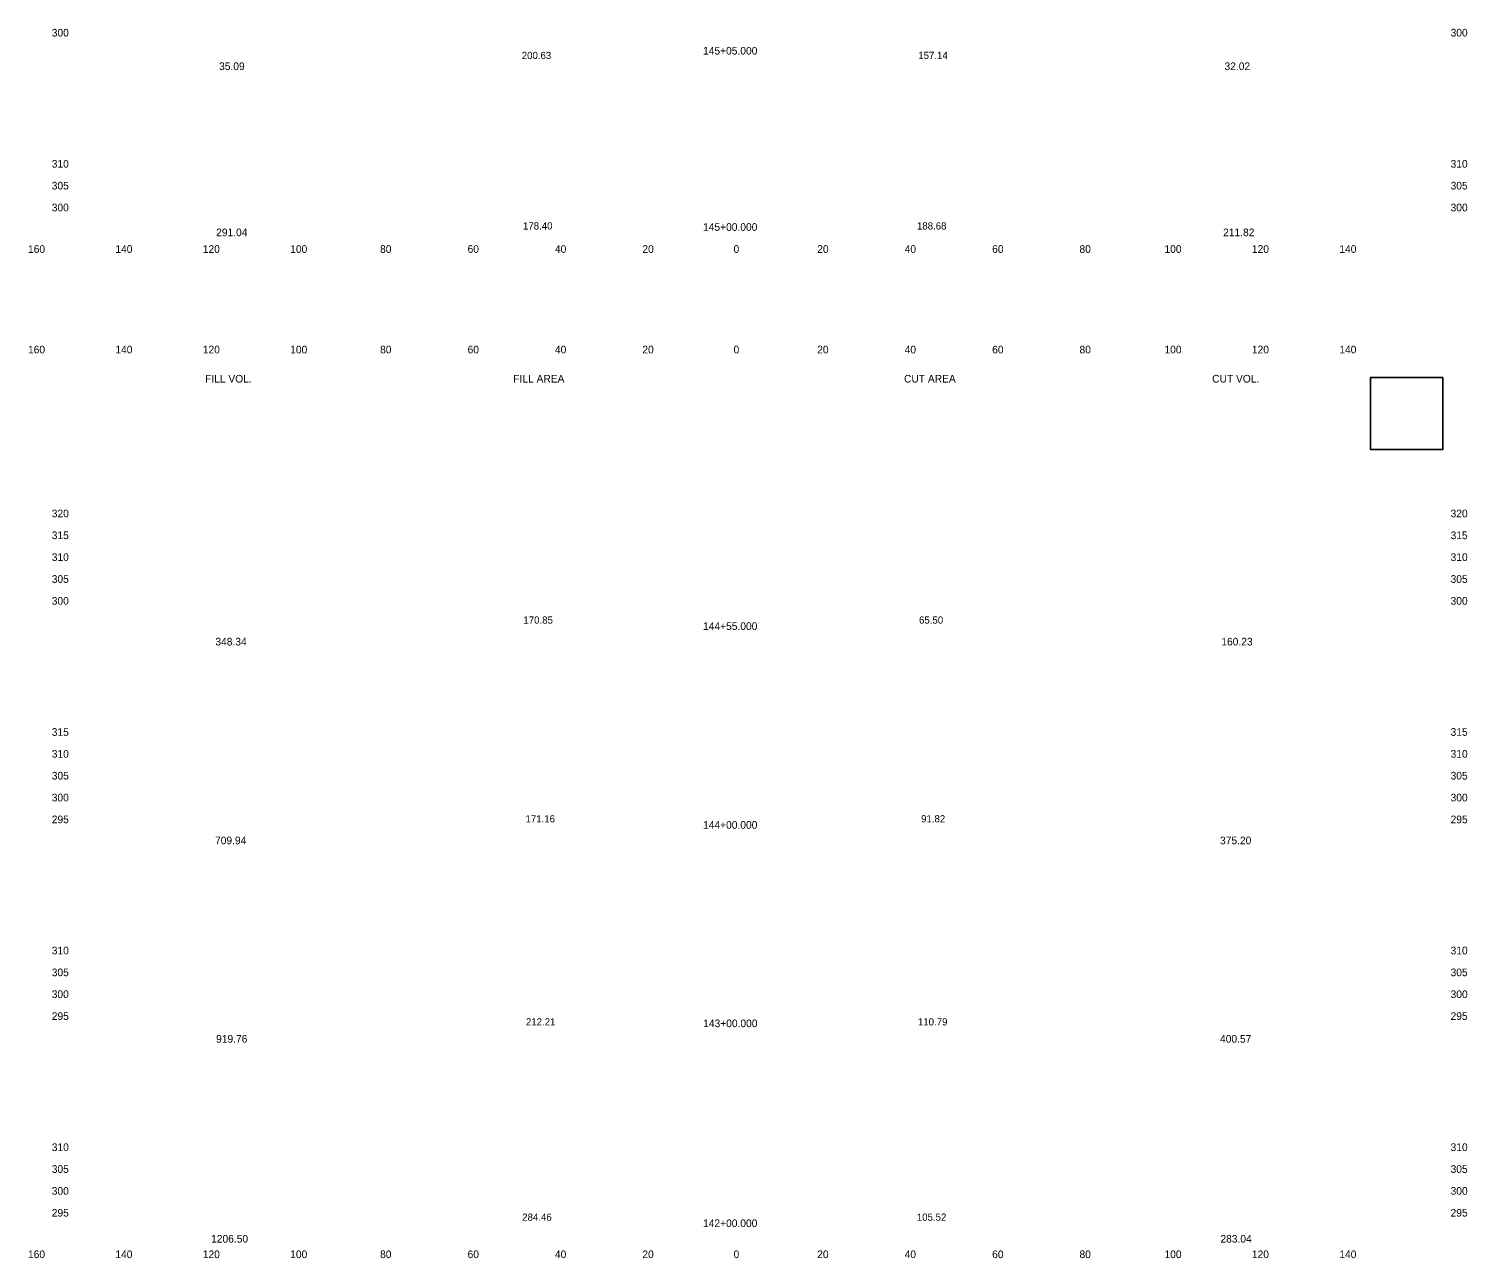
# Model space of a CAD drawing. Extents: x 21477 to 21806, y 6470 to 11049.
# Drawn here: x 21477.1 to 21806.1, y 9920.3 to 10201.6 of the extents above; entities that cross this region are included whole.
import ezdxf

# ---------------------------------------------------------------- set-up
doc = ezdxf.new("R2010")
doc.units = 0
for name, color, linetype in [('SHEET_CONSULTANT_STAMP', 7, 'Continuous'), ('XS_SHEET_EW_TX_AREA', 7, 'Continuous'), ('XS_SHEET_EW_TX_VOLUME', 7, 'Continuous'), ('XS_SHEET_LABELS_ELEVATION', 7, 'Continuous'), ('XS_SHEET_LABELS_OFFSET', 7, 'Continuous'), ('XS_SHEET_LABELS_STATION', 7, 'Continuous'), ('XS_SHEET_TX', 7, 'Continuous')]:
    doc.layers.add(name, color=color, linetype=linetype)

msp = doc.modelspace()

# ---------------------------------------------------------------- linework, layer by layer
at = {"layer": 'SHEET_CONSULTANT_STAMP'}
msp.add_lwpolyline([(21784.04, 10105.34), (21800.54, 10105.34), (21800.54, 10121.84), (21784.04, 10121.84)], close=True, dxfattribs=at)

# ---------------------------------------------------------------- texts
at = {"layer": 'XS_SHEET_EW_TX_AREA'}
for s, p in [(' 200.63 ', (21589.24, 10194.69)), (' 157.14 ', (21679.95, 10194.69)), (' 178.40 ', (21589.53, 10155.68)), (' 188.68 ', (21679.65, 10155.68)), (' 170.85 ', (21589.62, 10065.51)), (' 65.50 ', (21680.13, 10065.51)), (' 171.16 ', (21590.1, 10020.03)), (' 91.82 ', (21680.6, 10020.03)), (' 212.21 ', (21590.2, 9973.57)), (' 110.79 ', (21679.87, 9973.57)), (' 284.46 ', (21589.35, 9928.89)), (' 105.52 ', (21679.62, 9928.89))]:
    msp.add_text(s, height=1.65, dxfattribs=at).set_placement(p)
at = {"layer": 'XS_SHEET_EW_TX_VOLUME'}
for s, p in [(' 35.09 ', (21519.97, 10192.16)), (' 32.02 ', (21749.98, 10192.16)), (' 291.04 ', (21519.3, 10154.15)), (' 211.82 ', (21749.65, 10154.15)), (' 348.34 ', (21519.12, 10060.51)), (' 160.23 ', (21749.25, 10060.51)), (' 709.94 ', (21519.04, 10015.03)), (' 375.20 ', (21748.95, 10015.03)), (' 919.76 ', (21519.28, 9969.63)), (' 400.57 ', (21748.95, 9969.63)), (' 1206.50 ', (21518.14, 9923.89)), (' 283.04 ', (21749.04, 9923.89))]:
    msp.add_text(s, height=1.75, dxfattribs=at).set_placement(p)
at = {"layer": 'XS_SHEET_LABELS_ELEVATION'}
for s, p in [('  300  ', (21481.04, 10199.84)), ('  300  ', (21801.04, 10199.84)), ('  310  ', (21481.04, 10169.84)), ('  310  ', (21801.04, 10169.84)), ('  305  ', (21481.04, 10164.84)), ('  305  ', (21801.04, 10164.84)), ('  300  ', (21481.04, 10159.84)), ('  300  ', (21801.04, 10159.84)), ('  320  ', (21481.04, 10089.84)), ('  320  ', (21801.04, 10089.84)), ('  315  ', (21481.04, 10084.84)), ('  315  ', (21801.04, 10084.84)), ('  310  ', (21481.04, 10079.84)), ('  310  ', (21801.04, 10079.84)), ('  305  ', (21481.04, 10074.84)), ('  305  ', (21801.04, 10074.84)), ('  300  ', (21481.04, 10069.84)), ('  300  ', (21801.04, 10069.84)), ('  315  ', (21481.04, 10039.84)), ('  315  ', (21801.04, 10039.84)), ('  310  ', (21481.04, 10034.84)), ('  310  ', (21801.04, 10034.84)), ('  305  ', (21481.04, 10029.84)), ('  305  ', (21801.04, 10029.84)), ('  300  ', (21481.04, 10024.84)), ('  300  ', (21801.04, 10024.84)), ('  295  ', (21481.04, 10019.84)), ('  295  ', (21801.04, 10019.84)), ('  310  ', (21481.04, 9989.84)), ('  310  ', (21801.04, 9989.84)), ('  305  ', (21481.04, 9984.84)), ('  305  ', (21801.04, 9984.84)), ('  300  ', (21481.04, 9979.84)), ('  300  ', (21801.04, 9979.84)), ('  295  ', (21481.04, 9974.84)), ('  295  ', (21801.04, 9974.84)), ('  310  ', (21481.04, 9944.84)), ('  310  ', (21801.04, 9944.84)), ('  305  ', (21481.04, 9939.84)), ('  305  ', (21801.04, 9939.84)), ('  300  ', (21481.04, 9934.84)), ('  300  ', (21801.04, 9934.84)), ('  295  ', (21481.04, 9929.84)), ('  295  ', (21801.04, 9929.84))]:
    msp.add_text(s, height=1.75, dxfattribs=at).set_placement(p)
at = {"layer": 'XS_SHEET_LABELS_OFFSET'}
for s, p in [('  160  ', (21475.6, 10150.34)), ('  140  ', (21495.59, 10150.34)), ('  120  ', (21515.59, 10150.34)), ('  100  ', (21535.59, 10150.34)), ('  80  ', (21556.15, 10150.34)), ('  60  ', (21576.17, 10150.34)), ('  40  ', (21596.15, 10150.34)), ('  20  ', (21616.15, 10150.34)), ('  0  ', (21637.01, 10150.34)), ('  0  ', (21637.01, 10150.34)), ('  20  ', (21656.15, 10150.34)), ('  40  ', (21676.15, 10150.34)), ('  60  ', (21696.17, 10150.34)), ('  80  ', (21716.15, 10150.34)), ('  100  ', (21735.59, 10150.34)), ('  120  ', (21755.59, 10150.34)), ('  140  ', (21775.59, 10150.34)), ('  160  ', (21475.6, 10127.34)), ('  140  ', (21495.59, 10127.34)), ('  120  ', (21515.59, 10127.34)), ('  100  ', (21535.59, 10127.34)), ('  80  ', (21556.15, 10127.34)), ('  60  ', (21576.17, 10127.34)), ('  40  ', (21596.15, 10127.34)), ('  20  ', (21616.15, 10127.34)), ('  0  ', (21637.01, 10127.34)), ('  0  ', (21637.01, 10127.34)), ('  20  ', (21656.15, 10127.34)), ('  40  ', (21676.15, 10127.34)), ('  60  ', (21696.17, 10127.34)), ('  80  ', (21716.15, 10127.34)), ('  100  ', (21735.59, 10127.34)), ('  120  ', (21755.59, 10127.34)), ('  140  ', (21775.59, 10127.34)), ('  160  ', (21475.6, 9920.34)), ('  140  ', (21495.59, 9920.34)), ('  120  ', (21515.59, 9920.34)), ('  100  ', (21535.59, 9920.34)), ('  80  ', (21556.15, 9920.34)), ('  60  ', (21576.17, 9920.34)), ('  40  ', (21596.15, 9920.34)), ('  20  ', (21616.15, 9920.34)), ('  0  ', (21637.01, 9920.34)), ('  0  ', (21637.01, 9920.34)), ('  20  ', (21656.15, 9920.34)), ('  40  ', (21676.15, 9920.34)), ('  60  ', (21696.17, 9920.34)), ('  80  ', (21716.15, 9920.34)), ('  100  ', (21735.59, 9920.34)), ('  120  ', (21755.59, 9920.34)), ('  140  ', (21775.59, 9920.34))]:
    msp.add_text(s, height=1.75, dxfattribs=at).set_placement(p)
at = {"layer": 'XS_SHEET_LABELS_STATION'}
for s, p in [('  145+05.000  ', (21630.03, 10195.71)), ('  145+00.000  ', (21630.03, 10155.38)), ('  144+55.000  ', (21630.03, 10064.06)), ('  144+00.000  ', (21630.03, 10018.58)), ('  143+00.000  ', (21630.06, 9973.18)), ('  142+00.000  ', (21630.03, 9927.44))]:
    msp.add_text(s, height=1.75, dxfattribs=at).set_placement(p)
at = {"layer": 'XS_SHEET_TX'}
for s, p in [('FILL VOL.', (21517.41, 10120.67)), ('FILL AREA', (21587.92, 10120.67)), ('CUT AREA', (21677.31, 10120.67)), ('CUT VOL.', (21747.8, 10120.67))]:
    msp.add_text(s, height=1.75, dxfattribs=at).set_placement(p)

doc.saveas('drawing.dxf')
